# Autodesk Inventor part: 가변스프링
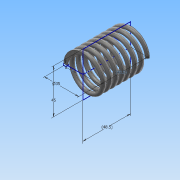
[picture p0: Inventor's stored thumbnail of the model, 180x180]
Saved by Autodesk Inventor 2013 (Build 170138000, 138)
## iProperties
Created: 2015-01
Part Number: 가변스프링
Material: 강철, 탄소
Document SubType Name: Modeling
Designer: Administrator
Density: 7.87 g/cm^3
Mass: 80.13 g
Surface Area: 103.219 cm^2
Volume: 10.1817 cm^3
Author: Administrator
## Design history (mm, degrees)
sketch "스케치1"
  geometry: L1 (0, 0)-(0, 48.5); L2 (0, 0)-(-17.5, 0); L3 (0, 48.5)-(-17.5, 48.5); C1 r 2 at (-17.5, 0)
  constraints: 6 end point, 1 centre point, 1 parallel, 1 perpendicular, 1 vertical
  dimensions: "d0" = 4 diameter of C1; "d1" = 48.5 distance of L1.start L1.end (derived); "d2" = 35 diameter of L2.end L1
feature "코일1" sketch "스케치1" pitch "d3" = 10; turns "d5" = 7.5; dims "d4" = 48.5 (= d1), "d6" = 0, angle "d7" = 90 deg, angle "d8" = 90 deg, "d9" = 0, "d10" = 0
sketch "스케치2"
  geometry: L1 (48.5, 22.5)-(0, 22.5); L2 (0, 22.5)-(0, -22.5); L3 (0, -22.5)-(48.5, -22.5); L4 (48.5, -22.5)-(48.5, 22.5); 2 further points
  constraints: 8 end point, 2 coincident, 2 parallel, 1 horizontal, 1 midpoint, 1 perpendicular
  dimensions: "d11" = 45 distance of L1.end L2.end; "d14" = 48.5 distance of L2.end L3.end (derived)
extrude "돌출1" sketch "스케치2" stored distance "d15" = 10; taper "d16" = 0 deg
node "솔리드1"
